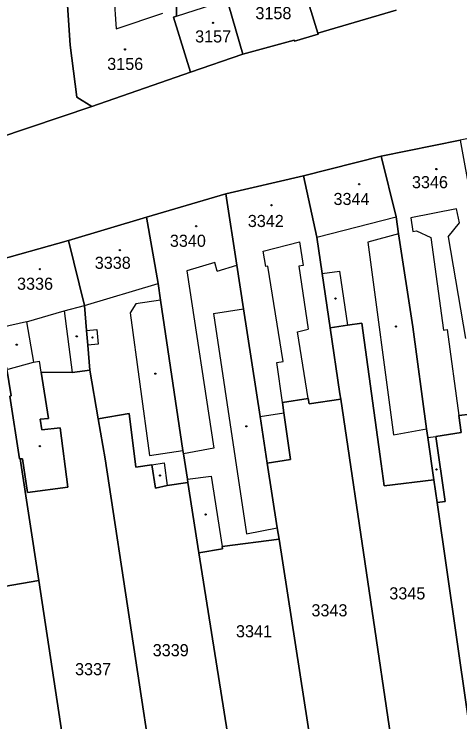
# Model space of a CAD drawing. Extents: x -596233 to -595156, y -1161235 to -1159375.
# Drawn here: x -595617.7 to -595555.1, y -1161138.1 to -1161038.8 of the extents above; entities that cross this region are included whole.
import ezdxf

# ---------------------------------------------------------------- set-up
doc = ezdxf.new("R2010")
doc.units = 0
for name, color, linetype in [('KN_CAR_KR', 7, 'Continuous'), ('KN_KULTURY', 7, 'Continuous'), ('KN_PARC_CIS_POZ', 7, 'Continuous'), ('KN_PARC_CIS_STAV', 7, 'Continuous'), ('KN_PARC_PLOCHA', 7, 'Continuous'), ('parcely_l', 7, 'Continuous')]:
    doc.layers.add(name, color=color, linetype=linetype)

msp = doc.modelspace()

# ---------------------------------------------------------------- linework, layer by layer
at = {"layer": 'KN_CAR_KR'}
for points in [[(-595603.74, -1161036.04), (-595603.42, -1161040.86)], [(-595594.92, -1161039.08), (-595589.82, -1161037.41)], [(-595603.42, -1161040.86), (-595596.86, -1161038.66)], [(-595555.58, -1161066.11), (-595562.01, -1161067.38)], [(-595555.19, -1161068.08), (-595555.58, -1161066.11)], [(-595575.22, -1161070.11), (-595564.08, -1161067.26)], [(-595562.01, -1161067.38), (-595561.74, -1161069.3)], [(-595556.75, -1161070.07), (-595555.19, -1161068.08)], [(-595563.74, -1161069.64), (-595568.03, -1161070.78)], [(-595561.74, -1161069.3), (-595561.21, -1161069.22)], [(-595561.21, -1161069.22), (-595559.22, -1161070.16)], [(-595582.78, -1161072.04), (-595577.64, -1161070.73)], [(-595577.64, -1161070.73), (-595577.14, -1161074.09)], [(-595568.03, -1161070.78), (-595564.46, -1161097.84)], [(-595559.22, -1161070.16), (-595557.44, -1161083.16)], [(-595556.75, -1161070.07), (-595554.33, -1161084.34)], [(-595582.38, -1161074.23), (-595582.78, -1161072.04)], [(-595589.55, -1161073.67), (-595593.5, -1161074.84)], [(-595589.2, -1161074.86), (-595589.55, -1161073.67)], [(-595589.2, -1161074.86), (-595586.46, -1161074.04)], [(-595582.08, -1161074.17), (-595582.38, -1161074.23)], [(-595579.94, -1161087.57), (-595582.08, -1161074.17)], [(-595577.14, -1161074.09), (-595577.76, -1161074.18)], [(-595577.76, -1161074.18), (-595576.45, -1161083.01)], [(-595593.5, -1161074.84), (-595589.7, -1161099.73)], [(-595574.47, -1161075.2), (-595572.04, -1161074.85)], [(-595572.04, -1161074.85), (-595570.92, -1161082.46)], [(-595607.88, -1161079.68), (-595597.52, -1161076.61)], [(-595610.73, -1161080.44), (-595607.88, -1161079.68)], [(-595600.64, -1161079.45), (-595601.43, -1161080.72)], [(-595597.17, -1161078.93), (-595600.64, -1161079.45)], [(-595615.99, -1161082), (-595610.73, -1161080.44)], [(-595610.73, -1161080.44), (-595609.57, -1161089.08)], [(-595601.43, -1161080.72), (-595598.73, -1161100.73)], [(-595589.74, -1161080.8), (-595585.52, -1161080.15)], [(-595589.74, -1161080.8), (-595585.1, -1161111.73)], [(-595615.99, -1161082), (-595619.53, -1161082.77)], [(-595615.99, -1161082), (-595615.02, -1161087.66)], [(-595607.57, -1161083.19), (-595606.12, -1161083.06)], [(-595606.12, -1161083.06), (-595605.94, -1161085.12)], [(-595577.94, -1161083.39), (-595576.45, -1161083.01)], [(-595576.44, -1161092.75), (-595577.94, -1161083.39)], [(-595557.44, -1161083.16), (-595556.9, -1161083.08)], [(-595556.9, -1161083.08), (-595555.25, -1161095.15)], [(-595605.94, -1161085.12), (-595607.4, -1161085.24)], [(-595618.56, -1161088.61), (-595615.02, -1161087.66)], [(-595615.02, -1161087.66), (-595614.2, -1161087.49)], [(-595613.96, -1161089.04), (-595614.2, -1161087.49)], [(-595580.83, -1161087.69), (-595579.94, -1161087.57)], [(-595580.05, -1161093.3), (-595580.83, -1161087.69)], [(-595583.19, -1161095.29), (-595579.84, -1161094.77)], [(-595564.46, -1161097.84), (-595559.81, -1161096.99)], [(-595559.63, -1161098.22), (-595558.5, -1161098.06)], [(-595598.73, -1161100.73), (-595594.03, -1161100.03)], [(-595589.7, -1161099.73), (-595593.96, -1161100.5)], [(-595598.38, -1161102.05), (-595596.66, -1161101.8)], [(-595596.66, -1161101.8), (-595596.24, -1161104.98)], [(-595593.39, -1161104.08), (-595590.08, -1161103.64)], [(-595590.08, -1161103.64), (-595588.5, -1161113.52)], [(-595585.1, -1161111.73), (-595580.78, -1161110.9)]]:
    msp.add_lwpolyline(points, dxfattribs=at)
at = {"layer": 'KN_KULTURY'}
for centre, radius in [((-595589.82, -1161040), 0.09), ((-595589.82, -1161040), 0.0398), ((-595602.17, -1161043.74), 0.09), ((-595602.17, -1161043.74), 0.0398), ((-595558.42, -1161060.53), 0.09), ((-595558.42, -1161060.53), 0.0398), ((-595569.27, -1161062.67), 0.09), ((-595569.27, -1161062.67), 0.0398), ((-595581.59, -1161065.62), 0.09), ((-595581.59, -1161065.62), 0.0398), ((-595592.17, -1161068.56), 0.09), ((-595592.17, -1161068.56), 0.0398), ((-595602.89, -1161071.91), 0.09), ((-595602.89, -1161071.91), 0.0398), ((-595614.14, -1161074.59), 0.09), ((-595614.14, -1161074.59), 0.0398), ((-595572.59, -1161078.72), 0.09), ((-595572.59, -1161078.72), 0.0398), ((-595564.08, -1161082.63), 0.09), ((-595564.08, -1161082.63), 0.0398), ((-595608.95, -1161084.02), 0.09), ((-595608.95, -1161084.02), 0.0398), ((-595606.74, -1161084.18), 0.09), ((-595606.74, -1161084.18), 0.0398), ((-595617.38, -1161085.19), 0.09), ((-595617.38, -1161085.19), 0.0398), ((-595597.91, -1161089.26), 0.09), ((-595597.91, -1161089.26), 0.0398), ((-595585.12, -1161096.65), 0.09), ((-595585.12, -1161096.65), 0.0398), ((-595614.14, -1161099.43), 0.09), ((-595614.14, -1161099.43), 0.0398), ((-595558.4, -1161102.7), 0.09), ((-595597.25, -1161103.56), 0.09), ((-595597.25, -1161103.56), 0.0398), ((-595558.4, -1161102.7), 0.0398), ((-595590.84, -1161109.03), 0.09), ((-595590.84, -1161109.03), 0.0398)]:
    msp.add_circle(centre, radius, dxfattribs=at)
at = {"layer": 'KN_PARC_PLOCHA'}
for points in [[(-595631.7, -1160897.5), (-595615.14, -1160895.31), (-595616.98, -1160898.71), (-595617.7, -1160902.65), (-595617.29, -1160919.81), (-595617.05, -1160922.72), (-595616.62, -1160941.37), (-595616.22, -1160946.87), (-595615.26, -1160961.87), (-595614.82, -1160968.76), (-595614.38, -1160975.64), (-595613.94, -1160982.53), (-595617.11, -1160982.74), (-595617.35, -1160987.8), (-595617.56, -1160996.69), (-595615.79, -1161018.89), (-595611.5, -1161018.59), (-595609.88, -1161043.14), (-595608.93, -1161050.44), (-595606.83, -1161051.74), (-595620.07, -1161056.19)], [(-595564.06, -1161038.23), (-595575.09, -1161041.45), (-595576.99, -1161035.16)], [(-595620.07, -1161056.19), (-595606.83, -1161051.74), (-595592.98, -1161046.93), (-595585.63, -1161044.42), (-595578.4, -1161042.42), (-595578.35, -1161042.58), (-595575.05, -1161041.61), (-595575.09, -1161041.45), (-595564.06, -1161038.23)], [(-595484.41, -1161042.49), (-595489.91, -1161043.55), (-595499.7, -1161045.45), (-595511, -1161047.65), (-595522.2, -1161049.89), (-595527.53, -1161050.96), (-595533.12, -1161052.08), (-595543.95, -1161054.25), (-595555.06, -1161056.48), (-595566.16, -1161058.7), (-595577.1, -1161061.5), (-595588.01, -1161064), (-595599.13, -1161067.3), (-595610.09, -1161070.58), (-595621.16, -1161073.65)]]:
    msp.add_lwpolyline(points, dxfattribs=at)
for points in [[(-595594.63, -1161014.5), (-595594.67, -1161017.04), (-595594.93, -1161025.3), (-595595.13, -1161025.3), (-595595.05, -1161032.3), (-595594.98, -1161036), (-595594.92, -1161039.08), (-595595.34, -1161039.19), (-595592.98, -1161046.93), (-595606.83, -1161051.74), (-595608.93, -1161050.44), (-595609.88, -1161043.14), (-595611.5, -1161018.59), (-595611.73, -1161015.32), (-595601.96, -1161014.6), (-595600.35, -1161014.49), (-595596.08, -1161014.2), (-595595.88, -1161014.16), (-595594.54, -1161014.06)], [(-595588.1, -1161014.59), (-595588.04, -1161017.11), (-595587.71, -1161031.73), (-595587.64, -1161034.69), (-595587.6, -1161036.68), (-595587.58, -1161037.63), (-595585.63, -1161044.42), (-595592.98, -1161046.93), (-595595.34, -1161039.19), (-595594.92, -1161039.08), (-595594.98, -1161036), (-595595.05, -1161032.3), (-595595.13, -1161025.3), (-595594.93, -1161025.3), (-595594.67, -1161017.04), (-595594.63, -1161014.5)], [(-595575.09, -1161041.45), (-595575.05, -1161041.61), (-595578.35, -1161042.58), (-595578.4, -1161042.42), (-595585.63, -1161044.42), (-595587.58, -1161037.63), (-595587.6, -1161036.68), (-595587.64, -1161034.69), (-595587.71, -1161031.73), (-595588.04, -1161017.11), (-595588.1, -1161014.59), (-595581.01, -1161014.6), (-595579.4, -1161014.6), (-595576.23, -1161014.59), (-595575.98, -1161014.59), (-595576.16, -1161015.95), (-595576.54, -1161018.87), (-595576.66, -1161019.95), (-595576.71, -1161020.41), (-595577.27, -1161025.17), (-595577.28, -1161030.89), (-595577.24, -1161034.09), (-595576.99, -1161035.16)], [(-595548.82, -1161093.64), (-595548.71, -1161094.38), (-595555.25, -1161095.15), (-595554.92, -1161097.54), (-595558.5, -1161098.06), (-595557.19, -1161107.2), (-595558.32, -1161107.36), (-595558.77, -1161104.18), (-595559.63, -1161098.22), (-595559.81, -1161096.99), (-595561.72, -1161082.7), (-595563.74, -1161069.64), (-595564.08, -1161067.26), (-595566.16, -1161058.7), (-595555.06, -1161056.48), (-595552.01, -1161073.41), (-595550.17, -1161083.63)], [(-595558.77, -1161104.18), (-595565.75, -1161105.01), (-595566.17, -1161101.93), (-595568.89, -1161082.16), (-595570.92, -1161082.46), (-595573.34, -1161082.82), (-595574.47, -1161075.2), (-595575.22, -1161070.11), (-595577.1, -1161061.5), (-595566.16, -1161058.7), (-595564.08, -1161067.26), (-595563.74, -1161069.64), (-595561.72, -1161082.7), (-595559.81, -1161096.99), (-595559.63, -1161098.22)], [(-595573.34, -1161082.82), (-595571.97, -1161092.07), (-595571.86, -1161092.83), (-595576.31, -1161093.51), (-595576.44, -1161092.75), (-595580.05, -1161093.3), (-595579.84, -1161094.77), (-595578.92, -1161101.3), (-595582.18, -1161101.81), (-595583.19, -1161095.29), (-595585.52, -1161080.15), (-595586.46, -1161074.04), (-595588.01, -1161064), (-595577.1, -1161061.5), (-595575.22, -1161070.11), (-595574.47, -1161075.2)], [(-595582.18, -1161101.81), (-595580.78, -1161110.9), (-595580.53, -1161112.48), (-595588.5, -1161113.52), (-595588.45, -1161113.86), (-595591.79, -1161114.43), (-595593.32, -1161104.52), (-595593.39, -1161104.08), (-595593.96, -1161100.5), (-595594.03, -1161100.03), (-595597.17, -1161078.93), (-595597.52, -1161076.61), (-595599.13, -1161067.3), (-595588.01, -1161064), (-595586.46, -1161074.04), (-595585.52, -1161080.15), (-595583.19, -1161095.29)], [(-595593.32, -1161104.52), (-595596.24, -1161104.98), (-595597.9, -1161105.31), (-595598.38, -1161102.05), (-595600.66, -1161102.38), (-595601.59, -1161094.86), (-595605.93, -1161095.6), (-595607.09, -1161088.75), (-595607.4, -1161085.24), (-595607.57, -1161083.19), (-595607.88, -1161079.68), (-595610.09, -1161070.58), (-595599.13, -1161067.3), (-595597.52, -1161076.61), (-595597.17, -1161078.93), (-595594.03, -1161100.03), (-595593.96, -1161100.5), (-595593.39, -1161104.08)], [(-595607.09, -1161088.75), (-595609.57, -1161089.08), (-595613.96, -1161089.04), (-595612.93, -1161095.54), (-595614.07, -1161095.65), (-595613.85, -1161097.15), (-595611.29, -1161096.84), (-595610.21, -1161105.21), (-595615.88, -1161105.95), (-595616.55, -1161101.2), (-595616.89, -1161101.2), (-595617.01, -1161101.2), (-595618.37, -1161092.42), (-595618.17, -1161092.39), (-595618.81, -1161088.35), (-595619.43, -1161084.4), (-595619.53, -1161082.77), (-595621.16, -1161073.65), (-595610.09, -1161070.58), (-595607.88, -1161079.68), (-595607.57, -1161083.19), (-595607.4, -1161085.24)], [(-595558.77, -1161104.18), (-595558.32, -1161107.36), (-595551.37, -1161155.6), (-595556.81, -1161156.4), (-595562.25, -1161157.2), (-595564.28, -1161144.11), (-595571.86, -1161092.83), (-595571.97, -1161092.07), (-595573.34, -1161082.82), (-595570.92, -1161082.46), (-595568.89, -1161082.16), (-595566.17, -1161101.93), (-595565.75, -1161105.01)], [(-595616.89, -1161101.2), (-595614.28, -1161118.28), (-595625.43, -1161120.2), (-595627.25, -1161108.52), (-595621.72, -1161107.66), (-595623.67, -1161088.91), (-595618.81, -1161088.35), (-595618.17, -1161092.39), (-595618.37, -1161092.42), (-595617.01, -1161101.2)], [(-595605.93, -1161095.6), (-595604.97, -1161101.22), (-595597.55, -1161149.9), (-595596.98, -1161153.69), (-595608.64, -1161155.34), (-595614.28, -1161118.28), (-595616.89, -1161101.2), (-595616.55, -1161101.2), (-595615.88, -1161105.95), (-595610.21, -1161105.21), (-595611.29, -1161096.84), (-595613.85, -1161097.15), (-595614.07, -1161095.65), (-595612.93, -1161095.54), (-595613.96, -1161089.04), (-595609.57, -1161089.08), (-595607.09, -1161088.75)], [(-595571.86, -1161092.83), (-595564.28, -1161144.11), (-595575.3, -1161146.03), (-595580.53, -1161112.48), (-595580.78, -1161110.9), (-595582.18, -1161101.81), (-595578.92, -1161101.3), (-595579.84, -1161094.77), (-595580.05, -1161093.3), (-595576.44, -1161092.75), (-595576.31, -1161093.51)], [(-595540.28, -1161147.46), (-595539.46, -1161153.84), (-595545.74, -1161154.77), (-595551.37, -1161155.6), (-595558.32, -1161107.36), (-595557.19, -1161107.2), (-595558.5, -1161098.06), (-595554.92, -1161097.54), (-595555.25, -1161095.15), (-595548.71, -1161094.38)], [(-595593.32, -1161104.52), (-595591.79, -1161114.43), (-595586.48, -1161147.97), (-595597.55, -1161149.9), (-595604.97, -1161101.22), (-595605.93, -1161095.6), (-595601.59, -1161094.86), (-595600.66, -1161102.38), (-595598.38, -1161102.05), (-595597.9, -1161105.31), (-595596.24, -1161104.98)], [(-595575.3, -1161146.03), (-595586.48, -1161147.97), (-595591.79, -1161114.43), (-595588.45, -1161113.86), (-595588.5, -1161113.52), (-595580.53, -1161112.48)], [(-595608.64, -1161155.34), (-595608.38, -1161157.05), (-595602.19, -1161197.61), (-595606.72, -1161198.36), (-595606.22, -1161201.36), (-595609.88, -1161201.89), (-595610.98, -1161194.32), (-595614.69, -1161194.86), (-595614.9, -1161192.89), (-595615.33, -1161189.95), (-595619.86, -1161158.8), (-595625.43, -1161120.2), (-595614.28, -1161118.28)]]:
    msp.add_lwpolyline(points, close=True, dxfattribs=at)
at = {"layer": 'parcely_l'}
for points in [[(-595594.63, -1161014.5), (-595594.67, -1161017.04), (-595594.93, -1161025.3), (-595595.13, -1161025.3), (-595595.05, -1161032.3), (-595594.98, -1161036), (-595594.92, -1161039.08), (-595595.34, -1161039.19), (-595592.98, -1161046.93)], [(-595585.63, -1161044.42), (-595587.58, -1161037.63), (-595587.6, -1161036.68), (-595587.64, -1161034.69), (-595587.71, -1161031.73), (-595588.04, -1161017.11), (-595588.1, -1161014.59)], [(-595575.09, -1161041.45), (-595576.99, -1161035.16), (-595577.24, -1161034.09), (-595577.28, -1161030.89), (-595577.27, -1161025.17), (-595576.71, -1161020.41), (-595576.66, -1161019.95), (-595576.54, -1161018.87), (-595576.16, -1161015.95), (-595575.98, -1161014.59), (-595576.23, -1161014.59)], [(-595606.83, -1161051.74), (-595608.93, -1161050.44), (-595609.88, -1161043.14), (-595611.5, -1161018.59)], [(-595564.06, -1161038.23), (-595575.09, -1161041.45)], [(-595585.63, -1161044.42), (-595578.4, -1161042.42), (-595578.35, -1161042.58), (-595575.05, -1161041.61), (-595575.09, -1161041.45)], [(-595592.98, -1161046.93), (-595585.63, -1161044.42)], [(-595606.83, -1161051.74), (-595592.98, -1161046.93)], [(-595620.07, -1161056.19), (-595606.83, -1161051.74)], [(-595555.06, -1161056.48), (-595566.16, -1161058.7)], [(-595577.1, -1161061.5), (-595566.16, -1161058.7)], [(-595566.16, -1161058.7), (-595564.08, -1161067.26), (-595563.74, -1161069.64), (-595561.72, -1161082.7), (-595559.81, -1161096.99), (-595559.63, -1161098.22), (-595558.77, -1161104.18)], [(-595577.1, -1161061.5), (-595588.01, -1161064)], [(-595573.34, -1161082.82), (-595574.47, -1161075.2), (-595575.22, -1161070.11), (-595577.1, -1161061.5)], [(-595588.01, -1161064), (-595599.13, -1161067.3)], [(-595588.01, -1161064), (-595586.46, -1161074.04), (-595585.52, -1161080.15), (-595583.19, -1161095.29), (-595582.18, -1161101.81)], [(-595599.13, -1161067.3), (-595610.09, -1161070.58)], [(-595593.32, -1161104.52), (-595593.39, -1161104.08), (-595593.96, -1161100.5), (-595594.03, -1161100.03), (-595597.17, -1161078.93), (-595597.52, -1161076.61), (-595599.13, -1161067.3)], [(-595610.09, -1161070.58), (-595621.16, -1161073.65)], [(-595610.09, -1161070.58), (-595607.88, -1161079.68), (-595607.57, -1161083.19), (-595607.4, -1161085.24), (-595607.09, -1161088.75)], [(-595573.34, -1161082.82), (-595570.92, -1161082.46), (-595568.89, -1161082.16), (-595566.17, -1161101.93), (-595565.75, -1161105.01), (-595558.77, -1161104.18)], [(-595571.86, -1161092.83), (-595571.97, -1161092.07), (-595573.34, -1161082.82)], [(-595616.89, -1161101.2), (-595617.01, -1161101.2), (-595618.37, -1161092.42), (-595618.17, -1161092.39), (-595618.81, -1161088.35)], [(-595607.09, -1161088.75), (-595609.57, -1161089.08), (-595613.96, -1161089.04), (-595612.93, -1161095.54), (-595614.07, -1161095.65), (-595613.85, -1161097.15), (-595611.29, -1161096.84), (-595610.21, -1161105.21), (-595615.88, -1161105.95), (-595616.55, -1161101.2), (-595616.89, -1161101.2)], [(-595605.93, -1161095.6), (-595607.09, -1161088.75)], [(-595582.18, -1161101.81), (-595578.92, -1161101.3), (-595579.84, -1161094.77), (-595580.05, -1161093.3), (-595576.44, -1161092.75), (-595576.31, -1161093.51), (-595571.86, -1161092.83)], [(-595564.28, -1161144.11), (-595571.86, -1161092.83)], [(-595558.32, -1161107.36), (-595557.19, -1161107.2), (-595558.5, -1161098.06), (-595554.92, -1161097.54), (-595555.25, -1161095.15), (-595548.71, -1161094.38)], [(-595605.93, -1161095.6), (-595601.59, -1161094.86), (-595600.66, -1161102.38), (-595598.38, -1161102.05), (-595597.9, -1161105.31), (-595596.24, -1161104.98), (-595593.32, -1161104.52)], [(-595597.55, -1161149.9), (-595604.97, -1161101.22), (-595605.93, -1161095.6)], [(-595616.89, -1161101.2), (-595614.28, -1161118.28)], [(-595582.18, -1161101.81), (-595580.78, -1161110.9), (-595580.53, -1161112.48)], [(-595591.79, -1161114.43), (-595593.32, -1161104.52)], [(-595558.77, -1161104.18), (-595558.32, -1161107.36)], [(-595551.37, -1161155.6), (-595558.32, -1161107.36)], [(-595580.53, -1161112.48), (-595588.5, -1161113.52), (-595588.45, -1161113.86), (-595591.79, -1161114.43)], [(-595575.3, -1161146.03), (-595580.53, -1161112.48)], [(-595591.79, -1161114.43), (-595586.48, -1161147.97)], [(-595625.43, -1161120.2), (-595614.28, -1161118.28)], [(-595614.28, -1161118.28), (-595608.64, -1161155.34)]]:
    msp.add_lwpolyline(points, dxfattribs=at)

# ---------------------------------------------------------------- texts
at = {"layer": 'KN_PARC_CIS_POZ'}
for s, p in [('3345', (-595565.0366, -1161120.95)), ('3343', (-595575.9766, -1161123.33)), ('3341', (-595586.5766, -1161126.27)), ('3339', (-595598.2766, -1161128.93)), ('3337', (-595609.1866, -1161131.59))]:
    msp.add_text(s, height=1.7, dxfattribs=at).set_placement(p)
at = {"layer": 'KN_PARC_CIS_STAV'}
for s, p in [('3158', (-595583.8466, -1161039.49)), ('3157', (-595592.3166, -1161042.76)), ('3156', (-595604.6666, -1161046.62)), ('3346', (-595561.8566, -1161063.22)), ('3344', (-595572.8766, -1161065.58)), ('3342', (-595584.9166, -1161068.67)), ('3340', (-595595.8666, -1161071.45)), ('3338', (-595606.4166, -1161074.54)), ('3336', (-595617.3366, -1161077.48))]:
    msp.add_text(s, height=1.7, dxfattribs=at).set_placement(p)

doc.saveas('drawing.dxf')
